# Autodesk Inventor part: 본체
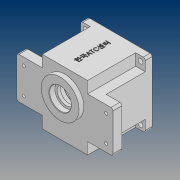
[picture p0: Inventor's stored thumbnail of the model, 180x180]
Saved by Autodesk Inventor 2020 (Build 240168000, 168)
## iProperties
Created: 2020-07
Part Number: 본체
Material: 일반
Document SubType Name: Modeling
Designer: PC312-
Density: 1 g/cm^3
Appearance: 기본값
Mass: 324.582 g
Surface Area: 793.906 cm^2
Volume: 324.582 cm^3
Author: PC312-
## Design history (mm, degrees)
sketch "스케치1"
  geometry: L1 (47, -47)-(-47, -47); L2 (-47, -47)-(-47, 47); L3 (-47, 47)-(47, 47); L4 (47, 47)-(47, -47); L5 (47, -47)-(-47, 47); L6 (-47, -47)-(47, 47); 1 further point
  constraints: 12 end point, 2 midpoint, 2 parallel, 1 horizontal, 1 perpendicular
  dimensions: "d0" = 94 distance of L2.end L3.end; "d1" = 94 distance of L1.end L2.end
extrude "돌출1" new body sketch "스케치1" distance "d2" = 67; taper "d3" = 0 deg
sketch "스케치2"
  geometry: L1 (-33, 30)-(-70, 30); L2 (-70, 30)-(-70, -30); L3 (-70, -30)-(-33, -30); L4 (-33, -30)-(-33, -47); L5 (-33, -47)-(33, -47); L6 (33, -47)-(33, -30); L7 (33, -30)-(70, -30); L8 (70, -30)-(70, 30); L9 (70, 30)-(33, 30); L10 (-33, 30)-(-33, 47); L11 (-33, 47)-(33, 47); L12 (33, 47)-(33, 30); L13 (47, 47)-(-47, 47) reference; L14 (-47, -47)-(47, -47) reference; L15 (0, 0)-(0, 77.106); L16 (0, 0)-(86.58, 0)
  constraints: 28 end point, 7 vertical, 5 horizontal, 5 point on line, 3 collinear, 3 other
  dimensions: "d4" = 140 distance between parallel lines of L2 L8; "d5" = 60 distance of L7.end L8.end; "d6" = 66 distance of L10.end L11.end
extrude "돌출2" join sketch "스케치2" distance "d7" = 13; taper "d8" = 0 deg
sketch "스케치3"
  geometry: L1 (-33, 30)-(-33, 47) reference; L2 (-33, 47)-(-47, 47) reference; L3 (-47, 47)-(-47, 30) reference; L4 (-47, 30)-(-33, 30) reference; L5 (33, 30)-(47, 30) reference; L6 (47, 30)-(47, 47) reference; L7 (47, 47)-(33, 47) reference; L8 (33, 47)-(33, 30) reference; L9 (-33, -47)-(-33, -30) reference; L10 (-33, -30)-(-47, -30) reference; L11 (-47, -30)-(-47, -47) reference; L12 (-47, -47)-(-33, -47) reference; L13 (47, -30)-(33, -30) reference; L14 (33, -30)-(33, -47) reference; L15 (33, -47)-(47, -47) reference; L16 (47, -47)-(47, -30) reference; 1 further point
extrude "돌출3" cut sketch "스케치3" distance "d9" = 57; taper "d10" = 0 deg
sketch "스케치4"
  geometry: L1 (0, 0)-(0, 66.5); L2 (0, 0)-(92.931, 0); 4 further points
  constraints: 4 end point, 2 symmetric about line, 1 horizontal, 1 horizontal alignment, 1 vertical, 1 vertical alignment
  dimensions: "d18" = 80 distance of point (40, 40) point (-40, 40); "d19" = 80 distance of point (40, -40) point (40, 40)
hole "구멍1" sketch "스케치4" at (40, 40), (40, -40), (-40, 40), (-40, -40) diameter "d11" = 7; stored, may be unused: countersink angle "d15" = 90 deg, drill point angle "d17" = 0 deg; dims "d12" = 8, "d13" = 4, "d14" = 2, "d16" = 10
sketch "스케치5"
  geometry: C1 r 27.5 at (0, 11); 1 further point
  constraints: 1 centre point, 1 vertical alignment
  dimensions: "d20" = 11 distance of point (0, 0) C1.centre; "d21" = 55 diameter of C1
extrude "돌출4" join sketch "스케치5" distance "d22" = 7; taper "d23" = 0 deg
sketch "스케치6"
  geometry: L1 (0, 0)-(0, 65.994); L2 (0, 0)-(-103.188, 0); 4 further points
  constraints: 4 end point, 2 symmetric about line, 1 horizontal, 1 horizontal alignment, 1 vertical, 1 vertical alignment
  dimensions: "d31" = 38 distance of point (-60, -19) point (-60, 19); "d32" = 120 distance of point (60, 19) point (-60, 19)
hole "구멍2" sketch "스케치6" at (60, 19), (60, -19), (-60, 19), (-60, -19) diameter "d24" = 4.5; stored, may be unused: countersink angle "d28" = 90 deg, drill point angle "d30" = 0 deg; dims "d25" = 8, "d26" = 10, "d27" = 5, "d29" = 10
sketch "스케치7"
  geometry: C1 r 43 at (0, 0); 1 further point
  constraints: 1 centre point, 1 coincident
  dimensions: "d33" = 86 diameter of C1
extrude "돌출5" cut sketch "스케치7" distance "d34" = 9; taper "d35" = 0 deg
sketch "스케치9"
  geometry: 2 further points
  constraints: 1 coincident
hole "구멍3" sketch "스케치9" at (0, 0) diameter "d36" = 80; stored, may be unused: countersink angle "d40" = 90 deg, drill point angle "d42" = 0 deg; dims "d37" = 8, "d38" = 10, "d39" = 5, "d41" = 62
sketch "스케치10"
  geometry: C1 r 27.5 at (0, 0) reference; 2 further points
  constraints: 1 coincident
hole "구멍4" sketch "스케치10" at (0, 0) diameter "d43" = 25; stored, may be unused: countersink angle "d47" = 90 deg, drill point angle "d49" = 0 deg; dims "d44" = 8, "d45" = 32, "d46" = 8.3, "d48" = 62
sketch "스케치11"
  geometry: C1 r 12.5 at (0, 11) reference; A1 r 21 centre (0, 11) between (8.978, -7.984) and (-8.978, -7.984); A2 r 15 centre (0, -20) between (-8.978, -7.984) and (8.978, -7.984); 1 further point
  constraints: 4 point on circle, 2 centre point, 1 coincident, 1 vertical alignment
  dimensions: "d52" = 20 distance of A2.centre point (0, 0); "d53" = 21 radius of A1; "d54" = 15 radius of A2
extrude "돌출6" join sketch "스케치11" distance "d55" = 7; taper "d56" = 0 deg
sketch "스케치12"
  geometry: A1 r 15 centre (0, -20) between (-8.978, -7.984) and (8.978, -7.984) reference; 2 further points
  constraints: 1 coincident
hole "구멍5" sketch "스케치12" at (0, -20) diameter "d57" = 19; stored, may be unused: countersink angle "d61" = 90 deg, drill point angle "d63" = 0 deg; dims "d58" = 8, "d59" = 22, "d60" = 7, "d62" = 10
sketch "스케치13"
  geometry: C1 r 12.5 at (0, 11) reference; 2 further points
  constraints: 1 coincident
hole "구멍6" sketch "스케치13" at (0, 11) diameter "d64" = 35; stored, may be unused: countersink angle "d68" = 90 deg, drill point angle "d70" = 0 deg; dims "d65" = 8, "d66" = 22, "d67" = 7, "d69" = 10
sketch "스케치14"
  geometry: L1 (35.777, 4)-(39.799, 4); L2 (35.777, -4)-(39.799, -4); A1 r 4 centre (36, 0) between (36, 4) and (36, -4); A2 r 36 centre (0, 0) between (36, 0) and (35.777, 4); A3 r 40 centre (0, 0) between (39.799, -4) and (39.799, 4) reference; 1 further point
  constraints: 7 point on circle, 4 end point, 2 centre point, 2 horizontal, 2 point on line, 2 tangent, 1 coincident, 1 horizontal alignment
  dimensions: "d71" = 8 diameter of A1; "d72" = 72 diameter of A2
extrude "돌출7" join sketch "스케치14" stored distance "d73" = 7; taper "d74" = 0 deg
sketch "스케치15"
  geometry: A1 r 4 centre (36, 0) between (36, 4) and (36, -4) reference; 2 further points
  constraints: 1 coincident
hole "구멍7" sketch "스케치15" at (36, 0) diameter "d75" = 3.242; stored, may be unused: countersink angle "d79" = 90 deg, drill point angle "d81" = 118 deg; dims "d76" = 7, "d77" = 22, "d78" = 7, "d80" = 9
chamfer "모따기1" distance "d85" = 0.8; stored, may be unused: second distance "d86" = 2, angle "d87" = 30 deg
fillet "모깎기1" dims "d88" = 3
fillet "모깎기2" dims "d89" = 3
fillet "모깎기3" dims "d90" = 3
chamfer "모따기2" distance "d91" = 1; stored, may be unused: second distance "d92" = 2, angle "d93" = 30 deg
node "작업 평면1"
sketch "스케치16"
  geometry: L1 (77, 80)-(-11, 80) reference; 2 further points
  constraints: 1 vertical alignment, 1 other
  dimensions: "d95" = 40 distance from line of point (33, 40) L1
feature "엠보싱1" sketch "스케치16" dims "d0" = 94, "d1" = 94, "d96" = 0.5, "d97" = 0
node "솔리드1"
pattern_circular "원형 패턴1" dims angle "d83" = 360 deg
node "투영된 루프1"
node "투영된 루프2"
node "투영된 루프3"
node "투영된 루프4"
feature "A9D066F2-1C7D-4E18-AEED-F7BC21143FA4" dims "d11" = 7, "d12" = 8, "d13" = 4, "d14" = 2, "d15" = 90 deg, "d16" = 10, "d17" = 0
other parameters: "d94" = 1
